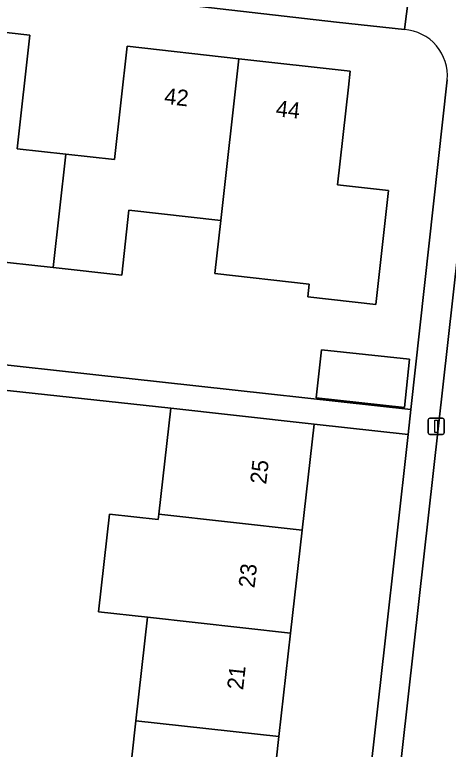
# Model space of a CAD drawing. Extents: x 162026 to 163502, y 387295 to 388169.
# Drawn here: x 162230.91 to 162257.68, y 387610.71 to 387656.09 of the extents above; entities that cross this region are included whole.
import ezdxf

# ---------------------------------------------------------------- set-up
doc = ezdxf.new("R2010")
doc.units = 0
for name, color, linetype in [('IMGEO_Erf', 7, 'Continuous'), ('IMGEO_Fietspad_gesloten', 7, 'Continuous'), ('IMGEO_Lichtmast', 7, 'Continuous'), ('IMGEO_Pand', 7, 'Continuous'), ('IMGEO_Pand_nummerreeks', 7, 'Continuous'), ('IMGEO_Voetpad_open', 7, 'Continuous')]:
    doc.layers.add(name, color=color, linetype=linetype)

msp = doc.modelspace()

# ---------------------------------------------------------------- linework, layer by layer
at = {"layer": 'IMGEO_Erf'}
for points in [[(162254.969, 387655.167), (162250.781, 387655.63), (162221.486, 387658.996)], [(162224.895, 387655.597), (162231.836, 387654.825), (162231.056, 387647.809), (162234.065, 387647.475), (162237.075, 387647.14), (162237.853, 387654.136), (162244.74, 387653.37), (162251.623, 387652.605), (162251.513, 387651.611), (162250.842, 387645.578), (162253.979, 387645.229), (162253.197, 387638.196), (162249.01, 387638.662), (162249.097, 387639.443), (162243.265, 387640.092), (162243.63, 387643.378), (162237.962, 387644.008), (162237.516, 387640.002), (162233.286, 387640.473), (162229.129, 387640.935)], [(162224.692, 387635.082), (162255.366, 387631.702), (162257.61, 387652.066)], [(162231.278, 387548.466), (162232.005, 387555.004), (162232.714, 387561.383), (162233.446, 387567.963), (162234.136, 387574.175), (162234.844, 387580.545), (162235.554, 387586.926), (162236.264, 387593.317), (162236.974, 387599.708), (162233.45, 387600.1), (162234.133, 387606.237), (162234.161, 387606.49), (162237.685, 387606.098), (162238.394, 387612.479), (162239.105, 387618.87), (162236.083, 387619.207), (162236.755, 387625.24), (162239.776, 387624.903), (162239.812, 387625.23), (162240.54, 387631.778), (162230.472, 387632.88)], [(162245.725, 387545.476), (162249.133, 387575.99), (162253.77, 387617.22), (162255.196, 387630.156), (162249.391, 387630.796), (162248.656, 387624.246), (162247.942, 387617.886), (162247.225, 387611.496), (162246.509, 387605.116), (162245.792, 387598.726), (162245.075, 387592.336), (162244.358, 387585.947), (162243.642, 387579.567), (162242.927, 387573.197), (162242.23, 387566.986), (162241.491, 387560.407), (162240.775, 387554.027), (162240.041, 387547.484)]]:
    msp.add_lwpolyline(points, dxfattribs=at)
msp.add_lwpolyline([(162249.844, 387635.394), (162255.288, 387634.807), (162254.967, 387631.83), (162249.523, 387632.416)], close=True, dxfattribs=at)
msp.add_arc((162254.781, 387652.332), 2.841, 354.6338, 86.2056, dxfattribs=at)
at = {"layer": 'IMGEO_Fietspad_gesloten'}
msp.add_lwpolyline([(162249.002, 387527.305), (162250.593, 387541.437), (162251.213, 387546.944), (162251.283, 387547.562), (162253.903, 387570.582), (162254.178, 387572.997), (162254.47, 387575.568), (162257.445, 387602.487), (162257.74, 387604.874), (162260.472, 387629.489), (162260.746, 387631.878), (162262.605, 387648.82), (162263.515, 387657.112), (162260.081, 387657.552), (162255.563, 387617.085), (162250.964, 387576.026), (162247.716, 387547.043), (162245.412, 387526.736)], dxfattribs=at)
at = {"layer": 'IMGEO_Lichtmast'}
for p, q in [((162256.439, 387630.26), (162256.439, 387631.06)), ((162256.439, 387631.06), (162256.439, 387630.26)), ((162256.539, 387631.16), (162257.329, 387631.16)), ((162257.329, 387631.16), (162256.539, 387631.16)), ((162257.429, 387631.06), (162257.429, 387630.26)), ((162257.429, 387630.26), (162257.429, 387631.06)), ((162257.329, 387630.16), (162256.539, 387630.16)), ((162256.539, 387630.16), (162257.329, 387630.16))]:
    msp.add_line(p, q, dxfattribs=at)
msp.add_lwpolyline([(162256.859, 387631.035), (162257.009, 387631.035), (162257.009, 387630.285), (162256.859, 387630.285), (162256.859, 387631.035)], dxfattribs=at)
for centre, start, end in [((162256.539, 387631.06), 90, 180), ((162256.539, 387631.06), 90, 180), ((162257.329, 387631.06), 0, 90), ((162257.329, 387631.06), 360, 90), ((162256.539, 387630.26), 180, 270), ((162256.539, 387630.26), 180, 270), ((162257.329, 387630.26), 270, 0), ((162257.329, 387630.26), 270, 0)]:
    msp.add_arc(centre, 0.1, start, end, dxfattribs=at)
at = {"layer": 'IMGEO_Pand'}
for points in [[(162234.065, 387647.475), (162231.056, 387647.809), (162231.836, 387654.825), (162224.895, 387655.597), (162223.786, 387645.639), (162229.58, 387644.995), (162229.129, 387640.935), (162233.286, 387640.473)], [(162244.74, 387653.37), (162237.853, 387654.136), (162237.075, 387647.14), (162234.065, 387647.475), (162233.286, 387640.473), (162237.516, 387640.002), (162237.962, 387644.008), (162243.63, 387643.378)], [(162251.513, 387651.611), (162251.623, 387652.605), (162244.74, 387653.37), (162243.63, 387643.378), (162243.265, 387640.092), (162249.097, 387639.443), (162249.01, 387638.662), (162253.197, 387638.196), (162253.979, 387645.229), (162250.842, 387645.578)], [(162249.523, 387632.416), (162254.967, 387631.83), (162255.288, 387634.807), (162249.844, 387635.394)], [(162248.656, 387624.246), (162249.391, 387630.796), (162244.422, 387631.347), (162240.54, 387631.778), (162239.812, 387625.23)], [(162248.656, 387624.246), (162239.812, 387625.23), (162239.776, 387624.903), (162236.755, 387625.24), (162236.083, 387619.207), (162239.105, 387618.87), (162247.942, 387617.886)], [(162247.225, 387611.496), (162247.942, 387617.886), (162239.105, 387618.87), (162238.394, 387612.479)], [(162246.509, 387605.116), (162247.225, 387611.496), (162238.394, 387612.479), (162237.685, 387606.098)]]:
    msp.add_lwpolyline(points, close=True, dxfattribs=at)
at = {"layer": 'IMGEO_Voetpad_open'}
for points in [[(162221.486, 387658.996), (162250.781, 387655.63), (162254.969, 387655.167), (162255.342, 387658.091), (162250.409, 387658.669), (162248.015, 387659.031), (162247.855, 387657.483), (162243.062, 387658.014), (162243.287, 387659.86), (162238.455, 387660.382), (162231.636, 387661.192), (162228.579, 387661.554), (162228.389, 387659.689), (162223.629, 387660.247), (162223.817, 387662.066), (162221.606, 387662.327), (162221.371, 387662.347)], [(162255.563, 387617.085), (162260.081, 387657.552), (162259.554, 387657.598), (162255.342, 387658.091), (162254.969, 387655.167)], [(162257.61, 387652.066), (162255.366, 387631.702), (162255.196, 387630.156), (162253.77, 387617.22), (162249.133, 387575.99), (162245.725, 387545.476), (162245.563, 387544.042), (162242.363, 387515.983)], [(162245.412, 387526.736), (162247.716, 387547.043), (162250.964, 387576.026), (162255.563, 387617.085)]]:
    msp.add_lwpolyline(points, dxfattribs=at)
msp.add_lwpolyline([(162224.692, 387635.082), (162224.519, 387633.556), (162229.488, 387632.992), (162230.472, 387632.88), (162240.54, 387631.778), (162244.422, 387631.347), (162249.391, 387630.796), (162255.196, 387630.156), (162255.366, 387631.702)], close=True, dxfattribs=at)
msp.add_arc((162254.781, 387652.332), 2.841, 354.6338, 86.2056, dxfattribs=at)

# ---------------------------------------------------------------- texts
at = {"layer": 'IMGEO_Pand_nummerreeks'}
for s, rotation, p in [('42', 353.6557, (162240.109, 387650.584)), ('44', 353.6574, (162246.997, 387649.819)), ('25', 83.5966, (162246.434, 387627.052)), ('23', 83.5945, (162245.715, 387620.644)), ('21', 83.5966, (162245.009, 387614.347))]:
    msp.add_text(s, height=1, rotation=rotation, dxfattribs=at).set_placement(p)

doc.saveas('drawing.dxf')
